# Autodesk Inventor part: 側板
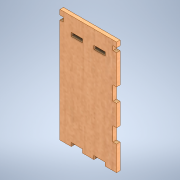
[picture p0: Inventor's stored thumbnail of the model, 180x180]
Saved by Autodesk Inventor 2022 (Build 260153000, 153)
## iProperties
Created: 2024-11
Part Number: 側板
Material: MDF 中密度繊維ボード
Document SubType Name: Modeling
Designer: shimizu
Density: 0.8 g/cm^3
Appearance: サクラ材 - ナチュラル 抑えた光沢
Author: shimizu
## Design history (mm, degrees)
sketch "スケッチ1"
  geometry: L1 (-20.243, 58.107)-(19.757, 58.107); L2 (-4.243, -21.893)-(-4.243, -19.393); L3 (-4.243, -19.393)-(-12.243, -19.393); L4 (-12.243, -19.393)-(-12.243, -21.893); L5 (11.757, -21.893)-(11.757, -19.393); L6 (11.757, -19.393)-(3.757, -19.393); L7 (3.757, -19.393)-(3.757, -21.893); L8 (-12.243, 48.107)-(-4.243, 48.107); L9 (-4.243, 48.107)-(-4.243, 45.607); L10 (-4.243, 45.607)-(-12.243, 45.607); L11 (-12.243, 45.607)-(-12.243, 48.107); L12 (3.757, 48.107)-(11.757, 48.107); L13 (11.757, 48.107)-(11.757, 45.607); L14 (11.757, 45.607)-(3.757, 45.607); L15 (3.757, 45.607)-(3.757, 48.107); L16 (-12.243, -21.893)-(-20.243, -21.893); L17 (19.757, -21.893)-(11.757, -21.893); L18 (3.757, -21.893)-(-4.243, -21.893); L19 (-20.243, 54.607)-(-17.743, 54.607); L20 (-17.743, 54.607)-(-17.743, 51.607); L21 (-17.743, 51.607)-(-20.243, 51.607); L22 (19.757, 54.607)-(17.257, 54.607); L23 (17.257, 54.607)-(17.257, 51.607); L24 (17.257, 51.607)-(19.757, 51.607); L25 (-20.243, -21.893)-(-20.243, 51.607); L26 (-20.243, 54.607)-(-20.243, 58.107); L27 (19.757, 58.107)-(19.757, 54.607); L28 (19.757, 51.607)-(19.757, -21.893); L29 (17.257, 30.607)-(19.757, 30.607); L30 (19.757, 30.607)-(19.757, 20.607); L31 (19.757, 20.607)-(17.257, 20.607); L32 (17.257, 20.607)-(17.257, 30.607); L33 (19.757, 5.607)-(17.257, 5.607); L34 (17.257, 5.607)-(17.257, -4.393); L35 (17.257, -4.393)-(19.757, -4.393); L36 (19.757, -4.393)-(19.757, 5.607); 3 further points
  constraints: 72 end point, 20 parallel, 9 perpendicular, 7 horizontal, 5 collinear, 2 point on line
  dimensions: "d27" = 80 distance between parallel lines of L17 L1; "d28" = 40 distance between parallel lines of L26 L27; "d29" = 10 distance between parallel lines of L31 L29; "d30" = 10 distance between parallel lines of L35 L33; "d31" = 2.5 distance of L30.end L31.end; "d32" = 2.5 distance of L34.end L35.end; "d33" = 15 distance between parallel lines of L6 L35; "d34" = 15 distance between parallel lines of L31 L33
extrude "押し出し1" new body sketch "スケッチ1" distance "d13" = 2.5; taper "d14" = 0 deg
node "ソリッド1"
